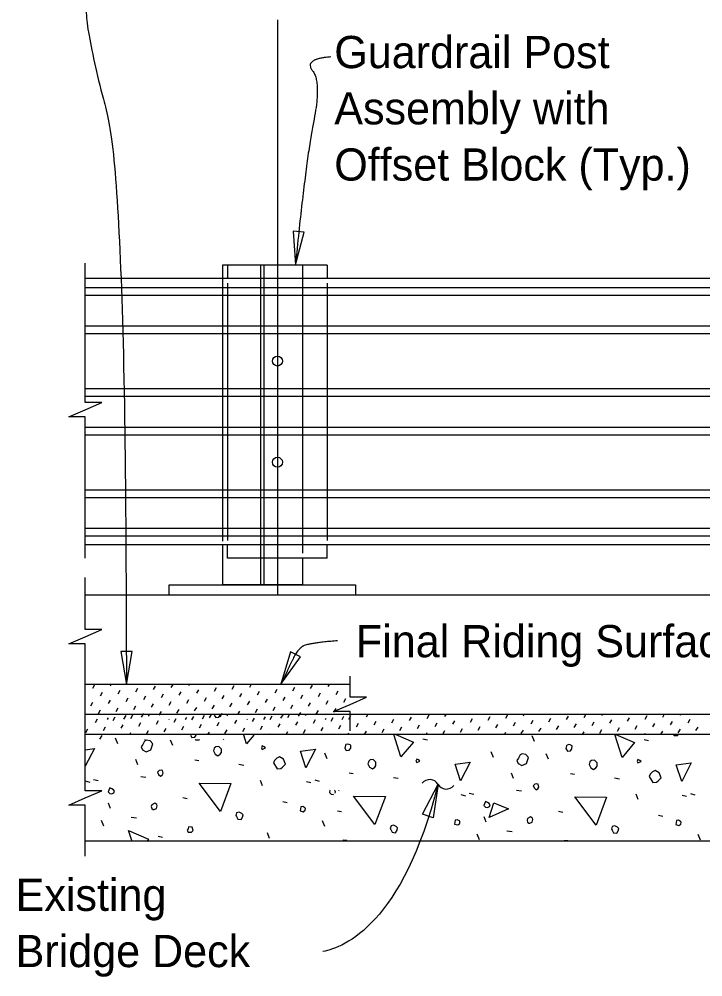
# Model space of a CAD drawing. Extents: x 21526.6 to 21595.9, y 56114.9 to 56157.2.
# Drawn here: x 21526.83 to 21531.11, y 56132.82 to 56138.81 of the extents above; entities that cross this region are included whole.
import ezdxf

# ---------------------------------------------------------------- set-up
doc = ezdxf.new("R2010")
doc.units = 0
for name, color, linetype in [('AdhocPoint_dp', 7, 'Continuous'), ('Border', 7, 'Continuous'), ('Patterning', 7, 'Continuous'), ('PlotBorder_dp', 7, 'Continuous'), ('SheetBorder_dp', 7, 'Continuous'), ('TextMisc', 7, 'Continuous')]:
    doc.layers.add(name, color=color, linetype=linetype)

msp = doc.modelspace()

# ---------------------------------------------------------------- linework, layer by layer
at = {"layer": 'AdhocPoint_dp'}
for p, q in [((21527.2426, 56135.21), (21535.6096, 56135.21)), ((21528.9006, 56134.6484), (21527.2426, 56134.6484)), ((21535.6096, 56134.46), (21527.2426, 56134.46)), ((21535.6096, 56134.335), (21527.2426, 56134.335)), ((21527.2426, 56133.6684), (21535.6096, 56133.6684))]:
    msp.add_line(p, q, dxfattribs=at)
at = {"layer": 'Patterning'}
for p, q in [((21528.4455, 56138.8093), (21528.4455, 56135.2123)), ((21528.758, 56137.2726), (21528.133, 56137.2726)), ((21528.133, 56137.2726), (21528.133, 56137.1892)), ((21528.758, 56137.2726), (21528.758, 56137.1892)), ((21528.133, 56137.1607), (21528.133, 56135.5488)), ((21528.758, 56137.1607), (21528.758, 56135.5488)), ((21528.133, 56135.4392), (21528.133, 56135.5226)), ((21528.758, 56135.4392), (21528.758, 56135.5226)), ((21528.758, 56135.4392), (21528.133, 56135.4392)), ((21527.2896, 56134.6259), (21527.3025, 56134.6483)), ((21527.3384, 56134.577), (21527.3514, 56134.5994)), ((21527.4002, 56134.6388), (21527.4057, 56134.6484)), ((21527.449, 56134.59), (21527.462, 56134.6124)), ((21527.5597, 56134.603), (21527.5726, 56134.6254)), ((21527.6703, 56134.6159), (21527.6833, 56134.6383)), ((21527.7809, 56134.6289), (21527.7922, 56134.6484)), ((21527.8298, 56134.5801), (21527.8427, 56134.6025)), ((21527.8916, 56134.6419), (21527.8953, 56134.6484)), ((21527.9404, 56134.593), (21527.9534, 56134.6154)), ((21528.051, 56134.606), (21528.064, 56134.6284)), ((21528.1617, 56134.619), (21528.1746, 56134.6413)), ((21528.2105, 56134.5701), (21528.2235, 56134.5925)), ((21528.2723, 56134.6319), (21528.2818, 56134.6484)), ((21528.3211, 56134.5831), (21528.3341, 56134.6055)), ((21528.3829, 56134.6449), (21528.3849, 56134.6484)), ((21528.4318, 56134.596), (21528.4447, 56134.6184)), ((21528.5424, 56134.609), (21528.5553, 56134.6314)), ((21528.653, 56134.622), (21528.666, 56134.6444)), ((21528.7019, 56134.5731), (21528.7148, 56134.5955)), ((21528.7637, 56134.6349), (21528.7714, 56134.6484)), ((21528.8125, 56134.5861), (21528.8254, 56134.6085)), ((21528.8743, 56134.6479), (21528.8745, 56134.6484)), ((21527.2766, 56134.5152), (21527.2896, 56134.5376)), ((21527.3872, 56134.5282), (21527.4002, 56134.5506)), ((21527.4979, 56134.5412), (21527.5108, 56134.5636)), ((21527.6085, 56134.5541), (21527.6215, 56134.5765)), ((21527.7191, 56134.5671), (21527.7321, 56134.5895)), ((21527.768, 56134.5183), (21527.7809, 56134.5407)), ((21527.8786, 56134.5312), (21527.8916, 56134.5536)), ((21527.9892, 56134.5442), (21528.0022, 56134.5666)), ((21528.0999, 56134.5572), (21528.1128, 56134.5795)), ((21528.2593, 56134.5213), (21528.2723, 56134.5437)), ((21528.37, 56134.5342), (21528.3829, 56134.5566)), ((21528.4806, 56134.5472), (21528.4936, 56134.5696)), ((21528.5912, 56134.5602), (21528.6042, 56134.5826)), ((21528.6401, 56134.5113), (21528.653, 56134.5337)), ((21528.7507, 56134.5243), (21528.7637, 56134.5467)), ((21528.8613, 56134.5373), (21528.8743, 56134.5597)), ((21527.3254, 56134.4664), (21527.3384, 56134.4888)), ((21527.4361, 56134.4794), (21527.449, 56134.5018)), ((21527.5467, 56134.4923), (21527.5597, 56134.5147)), ((21527.6573, 56134.5053), (21527.6703, 56134.5277)), ((21527.7062, 56134.4565), (21527.7191, 56134.4789)), ((21527.8168, 56134.4694), (21527.8298, 56134.4918)), ((21527.9274, 56134.4824), (21527.9404, 56134.5048)), ((21528.0381, 56134.4954), (21528.051, 56134.5177)), ((21528.1487, 56134.5083), (21528.1617, 56134.5307)), ((21528.1975, 56134.4595), (21528.2105, 56134.4819)), ((21528.3082, 56134.4724), (21528.3211, 56134.4948)), ((21528.4188, 56134.4854), (21528.4318, 56134.5078)), ((21528.5294, 56134.4984), (21528.5424, 56134.5208)), ((21528.5783, 56134.4495), (21528.5912, 56134.4719)), ((21528.6889, 56134.4625), (21528.7019, 56134.4849)), ((21528.7995, 56134.4755), (21528.8125, 56134.4979)), ((21528.9102, 56134.4884), (21528.9103, 56134.4886)), ((21527.2583, 56134.4585), (21527.2592, 56134.46)), ((21527.3071, 56134.4097), (21527.3201, 56134.4321)), ((21527.3811, 56134.4294), (21527.3872, 56134.44)), ((21527.4178, 56134.4226), (21527.4307, 56134.445)), ((21527.4849, 56134.4305), (21527.4979, 56134.4529)), ((21527.5284, 56134.4356), (21527.5413, 56134.458)), ((21527.5955, 56134.4435), (21527.6085, 56134.4659)), ((21527.639, 56134.4486), (21527.6457, 56134.46)), ((21527.6879, 56134.3997), (21527.7008, 56134.4221)), ((21527.7676, 56134.4294), (21527.768, 56134.43)), ((21527.7985, 56134.4127), (21527.8114, 56134.4351)), ((21527.8707, 56134.4294), (21527.8786, 56134.443)), ((21527.9091, 56134.4257), (21527.9221, 56134.4481)), ((21527.9763, 56134.4336), (21527.9892, 56134.4559)), ((21528.0198, 56134.4386), (21528.0321, 56134.46)), ((21528.0686, 56134.3898), (21528.0815, 56134.4122)), ((21528.0869, 56134.4465), (21528.0999, 56134.4689)), ((21528.1304, 56134.4516), (21528.1353, 56134.46)), ((21528.1792, 56134.4028), (21528.1922, 56134.4251)), ((21528.2572, 56134.4294), (21528.2593, 56134.433)), ((21528.2899, 56134.4157), (21528.3028, 56134.4381)), ((21528.3603, 56134.4294), (21528.37, 56134.446)), ((21528.4005, 56134.4287), (21528.4134, 56134.4511)), ((21528.4676, 56134.4366), (21528.4806, 56134.459)), ((21528.5111, 56134.4416), (21528.5218, 56134.46)), ((21528.56, 56134.3928), (21528.5729, 56134.4152)), ((21528.6217, 56134.4546), (21528.6249, 56134.46)), ((21528.6706, 56134.4058), (21528.6835, 56134.4282)), ((21528.7468, 56134.4294), (21528.7507, 56134.4361)), ((21528.7812, 56134.4187), (21528.7942, 56134.4411)), ((21528.8499, 56134.4294), (21528.8613, 56134.449)), ((21528.8918, 56134.4317), (21528.9048, 56134.4541)), ((21529.0025, 56134.4447), (21529.0114, 56134.46)), ((21529.0513, 56134.3958), (21529.0643, 56134.4182)), ((21529.1131, 56134.4576), (21529.1145, 56134.46)), ((21529.1619, 56134.4088), (21529.1749, 56134.4312)), ((21529.2726, 56134.4218), (21529.2855, 56134.4441)), ((21529.3832, 56134.4347), (21529.3962, 56134.4571)), ((21529.4938, 56134.4477), (21529.501, 56134.46)), ((21529.5427, 56134.3989), (21529.5556, 56134.4212)), ((21529.6533, 56134.4118), (21529.6663, 56134.4342)), ((21529.7639, 56134.4248), (21529.7769, 56134.4472)), ((21529.8746, 56134.4377), (21529.8875, 56134.46)), ((21529.9234, 56134.3889), (21529.9364, 56134.4113)), ((21529.9852, 56134.4507), (21529.9906, 56134.46)), ((21530.034, 56134.4019), (21530.047, 56134.4243)), ((21530.1447, 56134.4148), (21530.1576, 56134.4372)), ((21530.2553, 56134.4278), (21530.2683, 56134.4502)), ((21530.3659, 56134.4408), (21530.3771, 56134.46)), ((21530.4148, 56134.3919), (21530.4277, 56134.4143)), ((21530.4766, 56134.4537), (21530.4802, 56134.46)), ((21530.5254, 56134.4049), (21530.5384, 56134.4273)), ((21530.636, 56134.4179), (21530.649, 56134.4402)), ((21530.7467, 56134.4308), (21530.7596, 56134.4532)), ((21530.8573, 56134.4438), (21530.8667, 56134.46)), ((21530.9061, 56134.3949), (21530.9191, 56134.4173)), ((21530.9679, 56134.4567), (21530.9698, 56134.46)), ((21531.0168, 56134.4079), (21531.0297, 56134.4303)), ((21527.2453, 56134.3479), (21527.2583, 56134.3703)), ((21527.356, 56134.3608), (21527.3689, 56134.3832)), ((21527.4666, 56134.3738), (21527.4796, 56134.3962)), ((21527.5772, 56134.3868), (21527.5902, 56134.4092)), ((21527.6261, 56134.3379), (21527.639, 56134.3603)), ((21527.7367, 56134.3509), (21527.7497, 56134.3733)), ((21527.8473, 56134.3639), (21527.8603, 56134.3863)), ((21527.958, 56134.3768), (21527.9709, 56134.3992)), ((21528.1174, 56134.341), (21528.1304, 56134.3633)), ((21528.2281, 56134.3539), (21528.241, 56134.3763)), ((21528.3387, 56134.3669), (21528.3516, 56134.3893)), ((21528.4493, 56134.3798), (21528.4623, 56134.4022)), ((21528.5005, 56134.335), (21528.5111, 56134.3534)), ((21528.6088, 56134.344), (21528.6217, 56134.3664)), ((21528.7194, 56134.3569), (21528.7324, 56134.3793)), ((21528.8301, 56134.3699), (21528.843, 56134.3923)), ((21528.9407, 56134.3829), (21528.9536, 56134.4053)), ((21528.9901, 56134.335), (21529.0025, 56134.3564)), ((21529.1002, 56134.347), (21529.1131, 56134.3694)), ((21529.2108, 56134.36), (21529.2237, 56134.3824)), ((21529.3214, 56134.3729), (21529.3344, 56134.3953)), ((21529.432, 56134.3859), (21529.445, 56134.4083)), ((21529.4809, 56134.3371), (21529.4938, 56134.3594)), ((21529.5915, 56134.35), (21529.6045, 56134.3724)), ((21529.7021, 56134.363), (21529.7151, 56134.3854)), ((21529.8128, 56134.3759), (21529.8257, 56134.3983)), ((21529.9722, 56134.3401), (21529.9852, 56134.3625)), ((21530.0829, 56134.353), (21530.0958, 56134.3754)), ((21530.1935, 56134.366), (21530.2065, 56134.3884)), ((21530.3041, 56134.379), (21530.3171, 56134.4014)), ((21530.3558, 56134.335), (21530.3659, 56134.3525)), ((21530.4636, 56134.3431), (21530.4766, 56134.3655)), ((21530.5742, 56134.3561), (21530.5872, 56134.3784)), ((21530.6849, 56134.369), (21530.6978, 56134.3914)), ((21530.7955, 56134.382), (21530.8085, 56134.4044)), ((21530.8454, 56134.335), (21530.8573, 56134.3555)), ((21530.955, 56134.3461), (21530.9679, 56134.3685)), ((21531.0656, 56134.3591), (21531.0786, 56134.3815)), ((21527.3349, 56134.3055), (21527.3478, 56134.3279)), ((21527.4465, 56134.2767), (21527.4324, 56134.3121)), ((21527.5212, 56134.335), (21527.5284, 56134.3474)), ((21527.6176, 56134.3044), (21527.6179, 56134.305)), ((21527.7906, 56134.265), (21527.7765, 56134.3003)), ((21527.9077, 56134.335), (21527.9091, 56134.3374)), ((21528.0109, 56134.335), (21528.0198, 56134.3504)), ((21528.1072, 56134.3044), (21528.1093, 56134.308)), ((21528.3974, 56134.335), (21528.4005, 56134.3404)), ((21528.887, 56134.335), (21528.8918, 56134.3435)), ((21529.3562, 56134.3079), (21529.3845, 56134.3008)), ((21529.3766, 56134.335), (21529.3832, 56134.3465)), ((21529.7631, 56134.335), (21529.7639, 56134.3365)), ((21529.8662, 56134.335), (21529.8746, 56134.3495)), ((21530.0545, 56134.292), (21530.0403, 56134.3273)), ((21530.2527, 56134.335), (21530.2553, 56134.3396)), ((21530.7409, 56134.3043), (21530.7691, 56134.2973)), ((21530.7423, 56134.335), (21530.7467, 56134.3426)), ((21527.572, 56134.1442), (21527.5597, 56134.1777)), ((21527.9285, 56134.1766), (21527.9533, 56134.1731)), ((21528.7575, 56134.183), (21528.7434, 56134.2183)), ((21529.7981, 56134.1912), (21529.784, 56134.2266)), ((21530.1422, 56134.1795), (21530.1281, 56134.2148)), ((21528.2043, 56134.1483), (21528.2343, 56134.143)), ((21527.2945, 56134.054), (21527.3228, 56134.0469)), ((21527.5909, 56134.0723), (21527.6209, 56134.067)), ((21528.8954, 56134.0946), (21528.9202, 56134.0911)), ((21529.1712, 56134.0663), (21529.2012, 56134.061)), ((21529.9236, 56134.0586), (21529.9113, 56134.0922)), ((21530.2801, 56134.0911), (21530.3049, 56134.0875)), ((21530.5559, 56134.0628), (21530.5859, 56134.0575)), ((21527.2421, 56134.044), (21527.2704, 56134.037)), ((21528.3528, 56134.014), (21528.3404, 56134.0476)), ((21528.6268, 56134.0405), (21528.6551, 56134.0334)), ((21528.6792, 56134.0505), (21528.7075, 56134.0434)), ((21527.8543, 56133.9397), (21527.8808, 56133.9344)), ((21529.5937, 56133.9585), (21529.622, 56133.9514)), ((21529.6461, 56133.9685), (21529.6744, 56133.9614)), ((21529.9425, 56133.9868), (21529.9725, 56133.9815)), ((21530.7044, 56133.9284), (21530.692, 56133.962)), ((21530.9784, 56133.955), (21531.0067, 56133.9479)), ((21531.0308, 56133.9649), (21531.0591, 56133.9579)), ((21527.4006, 56133.8714), (21527.3882, 56133.905)), ((21528.48, 56133.915), (21528.5066, 56133.9097)), ((21527.5308, 56133.8177), (21527.5626, 56133.8142)), ((21528.8212, 56133.8577), (21528.8477, 56133.8524)), ((21529.7522, 56133.7859), (21529.7398, 56133.8195)), ((21530.2059, 56133.8542), (21530.2324, 56133.8489)), ((21530.8316, 56133.8294), (21530.8582, 56133.8241)), ((21527.3581, 56133.7618), (21527.344, 56133.7972)), ((21528.7428, 56133.7583), (21528.7287, 56133.7936)), ((21527.6987, 56133.6993), (21527.727, 56133.6922)), ((21528.397, 56133.6834), (21528.3828, 56133.7188)), ((21529.7097, 56133.6763), (21529.6956, 56133.7116)), ((21529.8824, 56133.7322), (21529.9142, 56133.7287)), ((21531.0944, 56133.6727), (21531.0803, 56133.7081))]:
    msp.add_line(p, q, dxfattribs=at)
for points in [[(21528.0505, 56134.4567), (21528.0591, 56134.4413), (21528.0785, 56134.443), (21528.0874, 56134.4554), (21528.0875, 56134.4567)], [(21527.6003, 56134.2396), (21527.6233, 56134.2272), (21527.6534, 56134.2396), (21527.6657, 56134.2767), (21527.6481, 56134.2944), (21527.6251, 56134.2997), (21527.6145, 56134.2927), (21527.6021, 56134.2732), (21527.5933, 56134.2573), (21527.6003, 56134.2396)], [(21527.9005, 56134.3317), (21527.9091, 56134.3163), (21527.9285, 56134.318), (21527.9373, 56134.3304), (21527.9375, 56134.3317)], [(21527.9326, 56134.3044), (21527.9336, 56134.302), (21527.9312, 56134.3044)], [(21527.9336, 56134.302), (21527.9548, 56134.302), (21527.9572, 56134.3044)], [(21528.252, 56134.2774), (21528.2343, 56134.3317)], [(21528.298, 56134.3317), (21528.252, 56134.2774)], [(21529.2189, 56134.1954), (21529.1735, 56134.335)], [(21529.1874, 56134.335), (21529.2967, 56134.2873), (21529.2189, 56134.1954)], [(21530.6036, 56134.1918), (21530.557, 56134.335)], [(21530.564, 56134.335), (21530.6814, 56134.2838), (21530.6036, 56134.1918)], [(21530.9257, 56134.335), (21530.9282, 56134.3291), (21530.9247, 56134.3326)], [(21530.9282, 56134.3291), (21530.9495, 56134.3291), (21530.9554, 56134.335)], [(21527.2426, 56134.2391), (21527.2998, 56134.2467), (21527.2427, 56134.1358)], [(21528.0452, 56134.2332), (21528.0558, 56134.212), (21528.0735, 56134.2014), (21528.0876, 56134.212), (21528.0947, 56134.2226), (21528.0947, 56134.2438), (21528.0788, 56134.2597), (21528.0593, 56134.2579), (21528.0505, 56134.2491), (21528.0452, 56134.2332)], [(21528.351, 56134.242), (21528.3704, 56134.2509), (21528.3634, 56134.2579), (21528.351, 56134.2632), (21528.3457, 56134.2509), (21528.351, 56134.242)], [(21528.6244, 56134.1265), (21528.5908, 56134.2308), (21528.6845, 56134.2432), (21528.6244, 56134.1265)], [(21528.8671, 56134.2502), (21528.876, 56134.2343), (21528.8954, 56134.236), (21528.9043, 56134.2484), (21528.906, 56134.2678), (21528.8937, 56134.2731), (21528.8848, 56134.2749), (21528.8742, 56134.2714), (21528.8707, 56134.2678), (21528.8671, 56134.2502)], [(21530.2518, 56134.2466), (21530.2607, 56134.2307), (21530.2801, 56134.2325), (21530.2889, 56134.2449), (21530.2907, 56134.2643), (21530.2783, 56134.2696), (21530.2695, 56134.2714), (21530.2589, 56134.2678), (21530.2554, 56134.2643), (21530.2518, 56134.2466)], [(21528.4217, 56134.1572), (21528.4447, 56134.12), (21528.4677, 56134.1218), (21528.4765, 56134.1306), (21528.496, 56134.1501), (21528.4836, 56134.1801), (21528.4588, 56134.1943), (21528.4412, 56134.1872), (21528.427, 56134.1731), (21528.4217, 56134.1572)], [(21529.0121, 56134.1512), (21529.0227, 56134.13), (21529.0404, 56134.1194), (21529.0545, 56134.13), (21529.0616, 56134.1406), (21529.0616, 56134.1618), (21529.0457, 56134.1777), (21529.0262, 56134.1759), (21529.0174, 56134.1671), (21529.0121, 56134.1512)], [(21529.3179, 56134.16), (21529.3374, 56134.1689), (21529.3303, 56134.1759), (21529.3179, 56134.1812), (21529.3126, 56134.1689), (21529.3179, 56134.16)], [(21529.9519, 56134.1541), (21529.9749, 56134.1417), (21530.005, 56134.1541), (21530.0173, 56134.1912), (21529.9997, 56134.2089), (21529.9767, 56134.2142), (21529.9661, 56134.2071), (21529.9537, 56134.1877), (21529.9449, 56134.1718), (21529.9519, 56134.1541)], [(21530.3968, 56134.1476), (21530.4074, 56134.1264), (21530.4251, 56134.1158), (21530.4392, 56134.1264), (21530.4463, 56134.137), (21530.4463, 56134.1582), (21530.4304, 56134.1742), (21530.4109, 56134.1724), (21530.4021, 56134.1635), (21530.3968, 56134.1476)], [(21530.7026, 56134.1565), (21530.722, 56134.1653), (21530.715, 56134.1724), (21530.7026, 56134.1777), (21530.6973, 56134.1653), (21530.7026, 56134.1565)], [(21529.5913, 56134.0445), (21529.5577, 56134.1488), (21529.6514, 56134.1612), (21529.5913, 56134.0445)], [(21530.976, 56134.0409), (21530.9424, 56134.1452), (21531.0361, 56134.1576), (21530.976, 56134.0409)], [(21527.7022, 56134.0847), (21527.7128, 56134.0741), (21527.7234, 56134.0811), (21527.7305, 56134.0918), (21527.727, 56134.1094), (21527.7181, 56134.1112), (21527.7058, 56134.1094), (21527.6952, 56134.0988), (21527.7022, 56134.0847)], [(21530.7733, 56134.0716), (21530.7963, 56134.0345), (21530.8193, 56134.0363), (21530.8281, 56134.0451), (21530.8476, 56134.0646), (21530.8352, 56134.0946), (21530.8104, 56134.1087), (21530.7928, 56134.1017), (21530.7786, 56134.0875), (21530.7733, 56134.0716)], [(21527.397, 56133.9656), (21527.4094, 56133.9638), (21527.4218, 56133.9692), (21527.4253, 56133.9798), (21527.42, 56133.9886), (21527.4094, 56133.9957), (21527.397, 56134.001), (21527.39, 56133.9868), (21527.3864, 56133.9762), (21527.397, 56133.9656)], [(21528.0894, 56133.8531), (21527.955, 56134.0299), (21528.1548, 56134.0281), (21528.0894, 56133.8531)], [(21530.0538, 56133.9991), (21530.0644, 56133.9885), (21530.075, 56133.9956), (21530.0821, 56134.0062), (21530.0786, 56134.0239), (21530.0697, 56134.0257), (21530.0574, 56134.0239), (21530.0468, 56134.0133), (21530.0538, 56133.9991)], [(21528.776, 56133.9861), (21528.7746, 56133.9833), (21528.7711, 56133.9727), (21528.7817, 56133.9621)], [(21528.7817, 56133.9621), (21528.7941, 56133.9603), (21528.796, 56133.9611)], [(21528.8073, 56133.9681), (21528.81, 56133.9762), (21528.8047, 56133.9851), (21528.8031, 56133.9861)], [(21528.8302, 56133.9823), (21528.8314, 56133.9861)], [(21529.0563, 56133.7711), (21528.9219, 56133.9479), (21529.1217, 56133.9461), (21529.0563, 56133.7711)], [(21530.441, 56133.7676), (21530.3066, 56133.9443), (21530.5064, 56133.9426), (21530.441, 56133.7676)], [(21527.6669, 56133.8655), (21527.6739, 56133.8655), (21527.6881, 56133.8725), (21527.6934, 56133.8885), (21527.6916, 56133.8973), (21527.6775, 56133.9044), (21527.6598, 56133.8938), (21527.6563, 56133.8832), (21527.6598, 56133.8725), (21527.6669, 56133.8655)], [(21528.5879, 56133.8566), (21528.6073, 56133.8513), (21528.6197, 56133.8602), (21528.6215, 56133.8725), (21528.6179, 56133.8761), (21528.6038, 56133.8832), (21528.5914, 56133.8814), (21528.5897, 56133.869), (21528.5879, 56133.8566)], [(21529.7486, 56133.8801), (21529.761, 56133.8783), (21529.7734, 56133.8836), (21529.7769, 56133.8942), (21529.7716, 56133.9031), (21529.761, 56133.9101), (21529.7486, 56133.9154), (21529.7416, 56133.9013), (21529.738, 56133.8907), (21529.7486, 56133.8801)], [(21529.771, 56133.8153), (21529.7993, 56133.9072), (21529.893, 56133.8701), (21529.771, 56133.8153)], [(21528.1884, 56133.8213), (21528.1972, 56133.8054), (21528.2184, 56133.8018), (21528.2273, 56133.8177), (21528.2308, 56133.8319), (21528.222, 56133.8407), (21528.206, 56133.8496), (21528.1901, 56133.8443), (21528.1848, 56133.8284), (21528.1884, 56133.8213)], [(21530.0185, 56133.7799), (21530.0255, 56133.7799), (21530.0397, 56133.787), (21530.045, 56133.8029), (21530.0432, 56133.8118), (21530.0291, 56133.8188), (21530.0114, 56133.8082), (21530.0079, 56133.7976), (21530.0114, 56133.787), (21530.0185, 56133.7799)], [(21527.8861, 56133.7241), (21527.9073, 56133.7241), (21527.9179, 56133.7347), (21527.9126, 56133.7541), (21527.8896, 56133.7559), (21527.8861, 56133.7453), (21527.8808, 56133.7364), (21527.8861, 56133.7241), (21527.8825, 56133.7276)], [(21529.1553, 56133.7393), (21529.1641, 56133.7234), (21529.1853, 56133.7198), (21529.1942, 56133.7357), (21529.1977, 56133.7499), (21529.1889, 56133.7587), (21529.173, 56133.7676), (21529.1571, 56133.7623), (21529.1518, 56133.7464), (21529.1553, 56133.7393)], [(21529.5548, 56133.7746), (21529.5742, 56133.7693), (21529.5866, 56133.7782), (21529.5884, 56133.7905), (21529.5849, 56133.7941), (21529.5707, 56133.8012), (21529.5583, 56133.7994), (21529.5566, 56133.787), (21529.5548, 56133.7746)], [(21530.54, 56133.7357), (21530.5488, 56133.7198), (21530.57, 56133.7163), (21530.5789, 56133.7322), (21530.5824, 56133.7464), (21530.5736, 56133.7552), (21530.5576, 56133.764), (21530.5417, 56133.7587), (21530.5364, 56133.7428), (21530.54, 56133.7357)], [(21530.9395, 56133.7711), (21530.9589, 56133.7658), (21530.9713, 56133.7746), (21530.9731, 56133.787), (21530.9695, 56133.7905), (21530.9554, 56133.7976), (21530.943, 56133.7959), (21530.9412, 56133.7835), (21530.9395, 56133.7711)], [(21527.536, 56133.665), (21527.5137, 56133.7335), (21527.6392, 56133.6787), (21527.6276, 56133.665)], [(21528.8805, 56133.6684), (21528.8795, 56133.6721), (21528.8565, 56133.6739), (21528.8547, 56133.6684)], [(21530.2643, 56133.6684), (21530.2642, 56133.6686), (21530.2412, 56133.6703), (21530.2406, 56133.6684)]]:
    msp.add_lwpolyline(points, dxfattribs=at)
at = {"layer": 'PlotBorder_dp'}
for points in [[(21528.5583, 56137.2748), (21528.614, 56137.4786), (21528.5438, 56137.4856)], [(21527.5005, 56134.6471), (21527.5357, 56134.8553), (21527.4652, 56134.8553)], [(21528.466, 56134.6497), (21528.5907, 56134.8202), (21528.5275, 56134.8517)], [(21529.4513, 56134.0231), (21529.4208, 56133.8141), (21529.3537, 56133.8358)]]:
    msp.add_lwpolyline(points, close=True, dxfattribs=at)
for points in [[(21527.2427, 56135.4395), (21527.2427, 56136.3228), (21527.1393, 56136.3228), (21527.2427, 56136.3678), (21527.346, 56136.4128), (21527.2427, 56136.4128), (21527.2427, 56137.2857)], [(21527.2427, 56134.3351), (21527.2427, 56134.9021), (21527.1393, 56134.9021), (21527.2427, 56134.9471), (21527.346, 56134.9921), (21527.2427, 56134.9921), (21527.2427, 56135.3182)], [(21528.9006, 56134.3576), (21528.9006, 56134.4784), (21528.7973, 56134.4784), (21528.9006, 56134.5234), (21529.004, 56134.5684), (21528.9006, 56134.5684), (21528.9006, 56134.699)], [(21527.2427, 56133.5727), (21527.2427, 56133.8927), (21527.1393, 56133.8927), (21527.2427, 56133.9377), (21527.346, 56133.9827), (21527.2427, 56133.9827), (21527.2427, 56134.3351)]]:
    msp.add_lwpolyline(points, dxfattribs=at)
for centre, start, end in [((21529.3989, 56133.9934), 30.00813, 141.73535), ((21529.5022, 56134.053), 210.00813, 321.73535)]:
    msp.add_arc(centre, 0.0596, start, end, dxfattribs=at)
for points, degree in [([(21527.3644, 56139.6956), (21527.0208, 56139.6041), (21527.2362, 56139.0828), (21527.253, 56138.6974), (21527.5005, 56137.7639), (21527.5005, 56134.6471)], 2), ([(21528.779, 56138.5761), (21528.6077, 56138.5632), (21528.7217, 56138.419), (21528.6236, 56137.9315), (21528.5583, 56137.2748)], 2), ([(21528.8223, 56134.922), (21528.6486, 56134.9066), (21528.5744, 56134.8752), (21528.5088, 56134.7353), (21528.466, 56134.6497)], 2), ([(21529.4505, 56134.0233), (21529.2298, 56133.1495), (21528.8654, 56133.0028), (21528.7303, 56132.976)], 3)]:
    msp.add_open_spline(points, degree=degree, dxfattribs=at)
at = {"layer": 'SheetBorder_dp'}
for p, q in [((21528.1017, 56137.2726), (21528.1017, 56135.5456)), ((21528.3413, 56135.2726), (21528.3413, 56137.2726)), ((21528.3622, 56135.2726), (21528.3622, 56137.2726)), ((21528.6017, 56137.2726), (21528.6017, 56135.4691))]:
    msp.add_line(p, q, dxfattribs=at)
at = {"layer": 'TextMisc'}
for p, q in [((21528.6017, 56137.2726), (21528.1017, 56137.2726)), ((21534.2788, 56137.1892), (21527.2426, 56137.1892)), ((21527.2426, 56137.1336), (21534.2788, 56137.1336)), ((21527.2426, 56137.0854), (21534.2788, 56137.0854)), ((21527.2426, 56136.8926), (21534.2788, 56136.8926)), ((21527.2426, 56136.8444), (21534.2788, 56136.8444)), ((21527.2426, 56136.5004), (21534.2788, 56136.5004)), ((21527.2426, 56136.4522), (21534.2788, 56136.4522)), ((21527.2426, 56136.2594), (21534.2788, 56136.2594)), ((21527.2426, 56136.2112), (21534.2788, 56136.2112)), ((21527.2426, 56135.8673), (21534.2788, 56135.8673)), ((21527.2426, 56135.8191), (21534.2788, 56135.8191)), ((21527.2426, 56135.6262), (21534.2788, 56135.6262)), ((21527.2426, 56135.578), (21534.2788, 56135.578)), ((21534.2788, 56135.5225), (21527.2426, 56135.5225)), ((21528.1017, 56135.5225), (21528.1017, 56135.2726)), ((21528.6017, 56135.4392), (21528.6017, 56135.2726)), ((21527.7684, 56135.2726), (21528.9351, 56135.2726)), ((21527.7684, 56135.2101), (21527.7684, 56135.2726)), ((21528.6017, 56135.2726), (21528.1017, 56135.2726)), ((21528.9351, 56135.2726), (21528.9351, 56135.2101)), ((21527.7684, 56135.2101), (21528.9351, 56135.2101))]:
    msp.add_line(p, q, dxfattribs=at)
for centre in [(21528.4455, 56136.6725), (21528.4455, 56136.0393)]:
    msp.add_circle(centre, 0.0312, dxfattribs=at)

# ---------------------------------------------------------------- texts
at = {"layer": 'Border'}
msp.add_text('Final Riding Surface', height=0.2016, dxfattribs=at).set_placement((21528.9369, 56134.8183))
at = {"layer": 'PlotBorder_dp'}
for s, p in [('Guardrail Post ', (21528.8015, 56138.506)), ('Assembly with ', (21528.8015, 56138.154)), ('Offset Block (Typ.)', (21528.8015, 56137.802)), ('Existing ', (21526.8068, 56133.2307)), ('Bridge Deck', (21526.8068, 56132.8787))]:
    msp.add_text(s, height=0.2016, dxfattribs=at).set_placement(p)

doc.saveas('drawing.dxf')
